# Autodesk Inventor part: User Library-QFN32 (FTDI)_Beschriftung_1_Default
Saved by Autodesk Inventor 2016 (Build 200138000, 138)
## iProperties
Created: 2012-01
Part Number: User Library-QFN32 (FTDI)_Beschriftung_1_Default
Document SubType Name: Modeling
Designer: Trevor
Density: 1 g/cm^3
Material: Generic
Appearance: Cool White
Author: Trevor
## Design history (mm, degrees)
feature "Base1"
node "Imported1"
